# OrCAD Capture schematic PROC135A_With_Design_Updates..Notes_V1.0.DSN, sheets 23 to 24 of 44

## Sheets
23 23. CPSW RGMII_2 ETHERNET CONN.: size C; title: CPSW3G RGMII_2 ETHERNET PHY
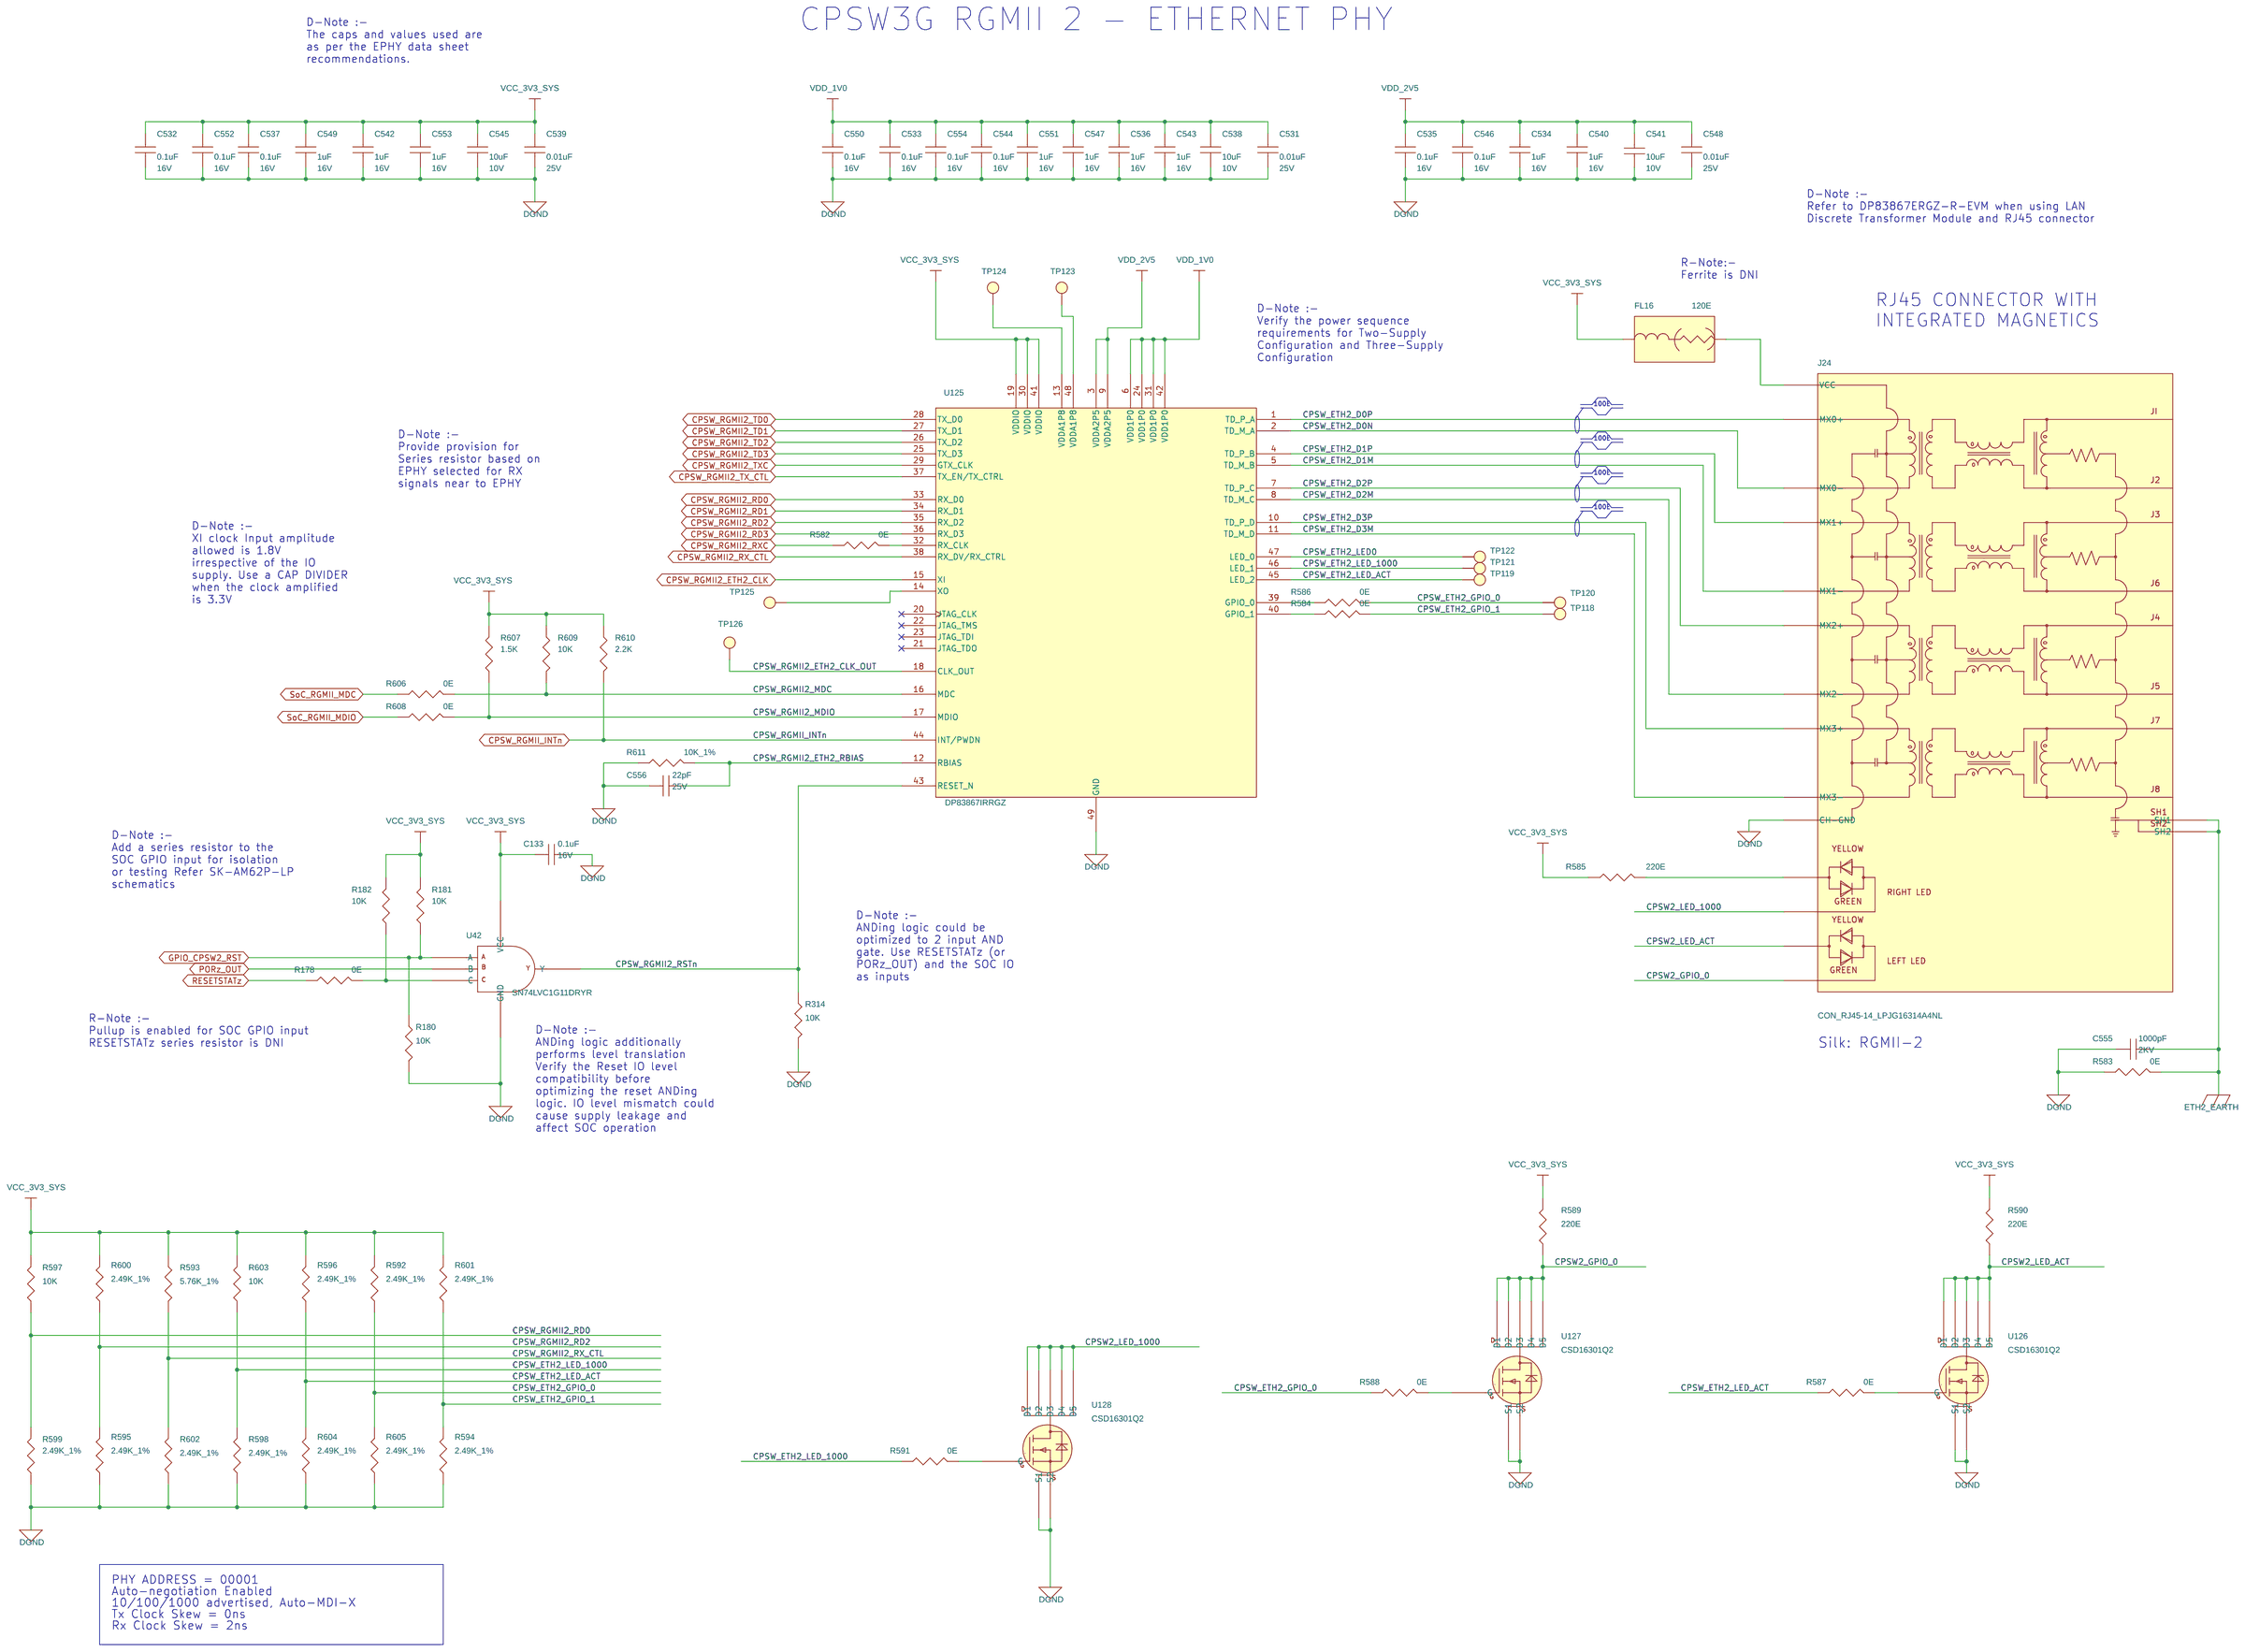
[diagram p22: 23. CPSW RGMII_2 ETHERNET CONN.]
24 24. PHY CLK & LED DRIVER: size C; title: SOC MAC INTERFACE, CLOCK BUFFER FOR SOC AND ETHERNET PHYS
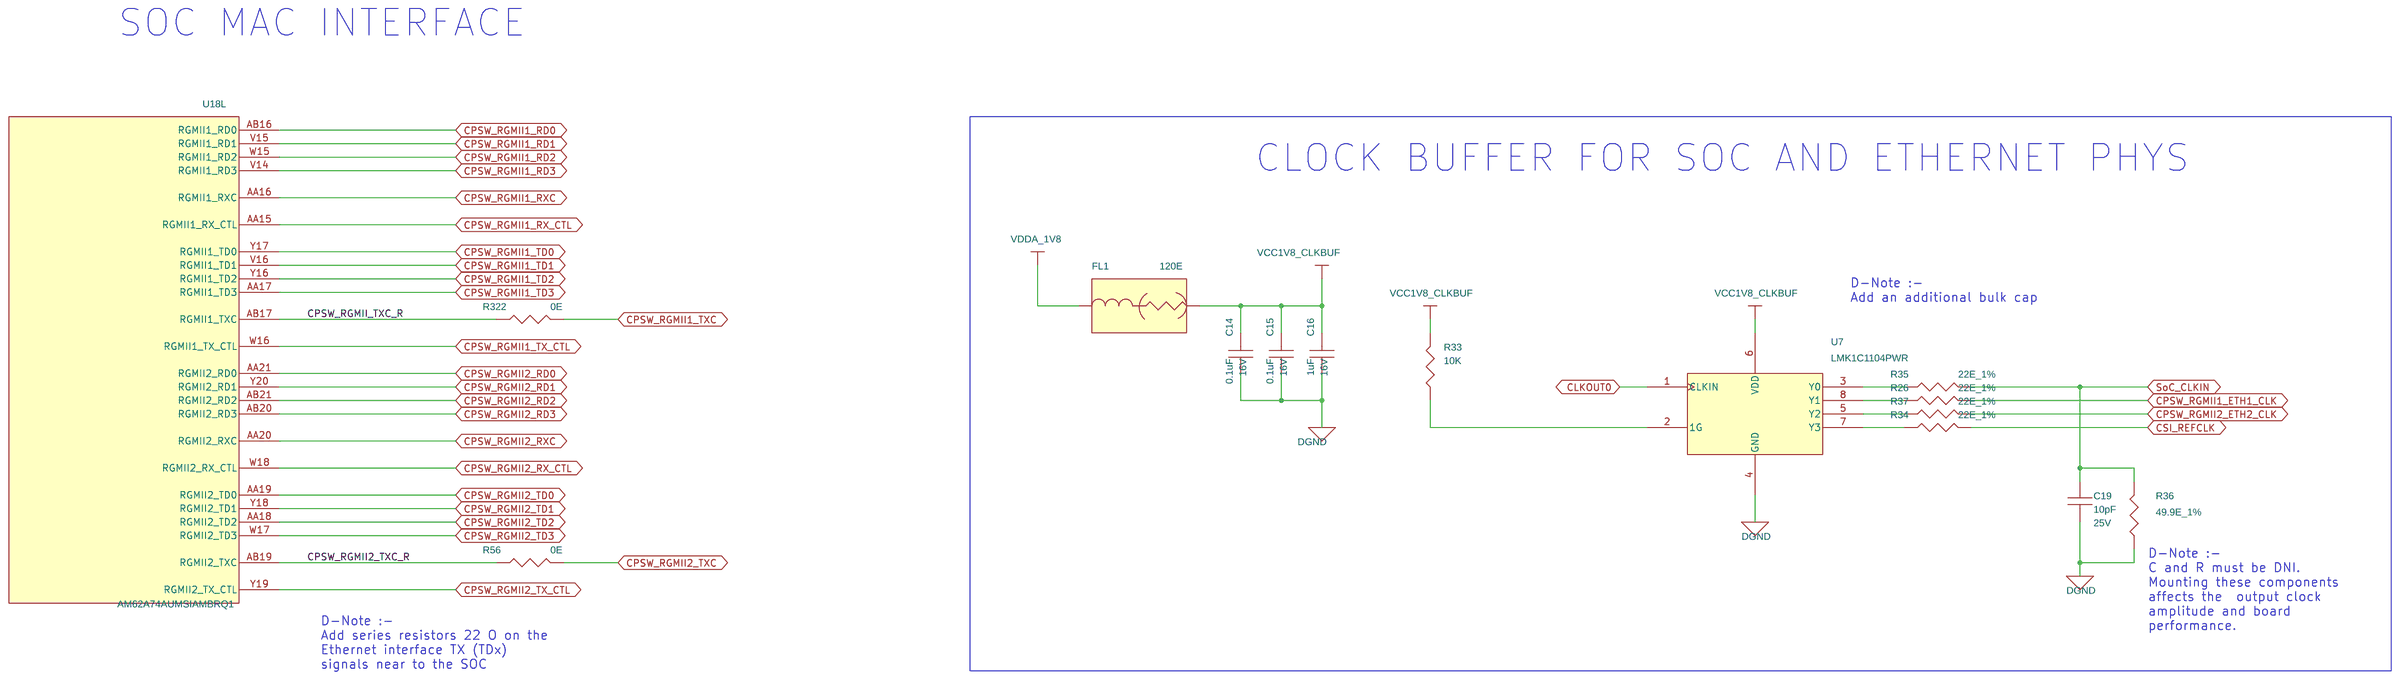
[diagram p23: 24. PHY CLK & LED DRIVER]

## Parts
sheet 23. CPSW RGMII_2 ETHERNET CONN.
C133  0.1uF  [CAP0201_0-5]
C531  0.01uF  [CAP0201_0-5]
C532  0.1uF  [CAP0201_0-5]
C533  0.1uF  [CAP0201_0-5]
C534  1uF  [CAP0201_0-5]
C535  0.1uF  [CAP0201_0-5]
C536  1uF  [CAP0201_0-5]
C537  0.1uF  [CAP0201_0-5]
C538  10uF  [CAP0402_0-75]
C539  0.01uF  [CAP0201_0-5]
C540  1uF  [CAP0201_0-5]
C541  10uF  [CAP0402_0-75]
C542  1uF  [CAP0201_0-5]
C543  1uF  [CAP0201_0-5]
C544  0.1uF  [CAP0201_0-5]
C545  10uF  [CAP0402_0-75]
C546  0.1uF  [CAP0201_0-5]
C547  1uF  [CAP0201_0-5]
C548  0.01uF  [CAP0201_0-5]
C549  1uF  [CAP0201_0-5]
C550  0.1uF  [CAP0201_0-5]
C551  1uF  [CAP0201_0-5]
C552  0.1uF  [CAP0201_0-5]
C553  1uF  [CAP0201_0-5]
C554  0.1uF  [CAP0201_0-5]
C555  1000pF  [CAP1206_1-75]
C556  22pF  [CAP0201_0-5]
FL16  120E  [EMIFIL_BLM15P_0402]
J24  CON_RJ45-14_LPJG16314A4NL  [CON_RJ45-14_LPJG16314A4NL_S_R_T_13-6]
R178  0E  [RES0201_0-5]
R180  10K  [RES0201_0-5]
R181  10K  [RES0201_0-5]
R182  10K  [RES0201_0-5]
R314  10K  [RES0201_0-5]
R582  0E  [RES0201_0-5]
R583  0E  [RES0603_0-75]
R584  0E  [RES0201_0-5]
R585  220E  [RES0402_0-5]
R586  0E  [RES0201_0-5]
R587  0E  [RES0402_0-5]
R588  0E  [RES0402_0-5]
R589  220E  [RES0402_0-5]
R590  220E  [RES0402_0-5]
R591  0E  [RES0402_0-5]
R592  2.49K_1%  [RES0402_0-5]
R593  5.76K_1%  [RES0402_0-5]
R594  2.49K_1%  [RES0402_0-5]
R595  2.49K_1%  [RES0402_0-5]
R596  2.49K_1%  [RES0402_0-5]
R597  10K  [RES0201_0-5]
R598  2.49K_1%  [RES0402_0-5]
R599  2.49K_1%  [RES0402_0-5]
R600  2.49K_1%  [RES0402_0-5]
R601  2.49K_1%  [RES0402_0-5]
R602  2.49K_1%  [RES0402_0-5]
R603  10K  [RES0201_0-5]
R604  2.49K_1%  [RES0402_0-5]
R605  2.49K_1%  [RES0402_0-5]
R606  0E  [RES0402_0-5]
R607  1.5K  [RES0201_0-5]
R608  0E  [RES0402_0-5]
R609  10K  [RES0201_0-5]
R610  2.2K  [RES0201_0-5]
R611  10K_1%  [RES0402_0-5]
TP118  TP20_SMD  [TP20_SMD]
TP119  TP20_SMD  [TP20_SMD]
TP120  TP20_SMD  [TP20_SMD]
TP121  TP20_SMD  [TP20_SMD]
TP122  TP20_SMD  [TP20_SMD]
TP123  TP20_SMD  [TP20_SMD]
TP124  TP20_SMD  [TP20_SMD]
TP125  TP20_SMD  [TP20_SMD]
TP126  TP20_SMD  [TP20_SMD]
U42  SN74LVC1G11DRYR  [SON6_SN74LVC2G17_40X60_0-6]
U125  DP83867IRRGZ  [QFN48_19-68_280X280_1]
U126  CSD16301Q2  [WSON6_CSD13202Q2_80X80_0-8]
U127  CSD16301Q2  [WSON6_CSD13202Q2_80X80_0-8]
U128  CSD16301Q2  [WSON6_CSD13202Q2_80X80_0-8]
sheet 24. PHY CLK & LED DRIVER
C14  0.1uF  [CAP0201_0-5]
C15  0.1uF  [CAP0201_0-5]
C16  1uF  [CAP0201_0-5]
C19  10pF  [CAP0201_0-5]
FL1  120E  [EMIFIL_BLM15A_0402_0-6]
R26  22E_1%  [RES0201_0-5]
R33  10K  [RES0201_0-5]
R34  22E_1%  [RES0201_0-5]
R35  22E_1%  [RES0201_0-5]
R36  49.9E_1%  [RES0402_0-5]
R37  22E_1%  [RES0201_0-5]
R56  0E  [RES0201_0-5]
R322  0E  [RES0201_0-5]
U7  LMK1C1104PWR  [TSSOP8_25-59_125X180_1-2]
sheet 41. OSCILLATOR
U18  AM62A74AUMSIAMBRQ1  [FBGA484_31-49_710X710_2-7]  (sections A,B,C,D,E,F,G,H,I,J,K,L,M,N,O,P,Q)

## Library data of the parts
C14 C15 C133 C532 C533 C535 C537 C544 C546 C550 C552 C554 = CAP: CAP CERAMIC 0.1uF 16V 10% X5R 0201; Alt_Mfr_name: YAGEO AMERICA; Alt_Mfr_part_number: CC0402KRX5R8BB104; Chkd/date: MANIRAJA/230118; Crtd /date: MANIRAJA/230118; Custom_Duty: 15%; Customs_HS_Code: 85322990; Distributor_name: DIGIKEY; Distributor_part_number: 490-14305-1-ND; Footprint Path: Y:\MIS_DATABASE\Library\ALTIUM_TOOL\PCB_FOOTPRINTS\Altium_Footprint_Lib.PcbLib; Height: 0.33MM; Library Path: Y:\MIS_DATABASE\Library\ALTIUM_TOOL\SCHEMATICS_PARTS\MS_DISCRETE_Library.schlib; Mfr_name: MURATA; Mfr_part_number: GRM033R61C104KE14D; Mistral Part No: 120009030072-R; Package: 0201; Part_type: CAPACITORS\CERAMIC; Project: TI_MAXIE_CPB; RoHS: RoHS; Temperature: -55°C+85°C; Tolerance: 10%; Voltage: 16V; Wattage: NA; Weight: 0.33mg; Datasheet: Y:\MIS_DATABASE\DATASHEETS\CAPACITORS\GRM033R61C104KE14.PDF
C531 C539 C548 = CAP: CAP CERAMIC 0.01uF 25V 10% X5R 0201; Chkd/date: MANIRAJA/230118; Crtd /date: MANIRAJA/230118; Custom_Duty: 15%; Customs_HS_Code: 85322990; Distributor_name: DIGIKEY; Distributor_part_number: GRM033R61E103KA12J-ND; Footprint Path: Y:\MIS_DATABASE\Library\ALTIUM_TOOL\PCB_FOOTPRINTS\Altium_Footprint_Lib.PcbLib; Height: 0.33MM; Library Path: Y:\MIS_DATABASE\Library\ALTIUM_TOOL\SCHEMATICS_PARTS\MS_DISCRETE_Library.schlib; Mfr_name: MURATA; Mfr_part_number: GRM033R61E103KA12J; Mistral Part No: 120018010007-R; Package: 0201; Part_type: CAPACITORS\CERAMIC; Project: TI_MAXIE_CPB; RoHS: RoHS; Temperature: -55°C+85°C; Tolerance: 10%; Voltage: 25V; Wattage: NA; Weight: 0.33mg; Datasheet: Y:\MIS_DATABASE\DATASHEETS\CAPACITORS\GRM033R61E103KA12.PDF
C16 C534 C536 C540 C542 C543 C547 C549 C551 C553 = CAP: CAP CERAMIC 1uF 16V 20% X5R 0201; Chkd/date: MANIRAJA/300520; Crtd /date: ALVY/260520; Custom_Duty: 15%; Customs_HS_Code: 85322990; Distributor_name: DIGIKEY; Distributor_part_number: 490-18654-1-ND; Footprint Path: Y:\MIS_DATABASE\Library\ALTIUM_TOOL\PCB_FOOTPRINTS\Altium_Footprint_Lib.PcbLib; Height: 0.39MM; Library Path: Y:\MIS_DATABASE\Library\ALTIUM_TOOL\SCHEMATICS_PARTS\MS_DISCRETE_Library.schlib; Mfr_name: MURATA; Mfr_part_number: GRM033R61C105ME15D; Mistral Part No: 120018090038-R; Package: 0201; Part_type: CAPACITORS\CERAMIC; Project: QCS610_NANOSOM; RoHS: RoHS; Temperature: -55°C+85°C; Tolerance: 20%; Voltage: 16V; Wattage: NA; Weight: 0.33mg; Datasheet: Y:\MIS_DATABASE\DATASHEETS\CAPACITORS\GRM033R61C105ME15.PDF
C538 C541 C545 = CAP: CAP CERAMIC 10uF 10V 20% X5R 0402; Chkd/date: MANIRAJA/300520; Crtd /date: ALVY/260520; Custom_Duty: 15%; Customs_HS_Code: 85322990; Distributor_name: DIGIKEY; Distributor_part_number: 490-GRM155R61A106ME11DTR-ND; Footprint Path: Y:\MIS_DATABASE\Library\ALTIUM_TOOL\PCB_FOOTPRINTS\Altium_Footprint_Lib.PcbLib; Height: 0.55MM; Library Path: Y:\MIS_DATABASE\Library\ALTIUM_TOOL\SCHEMATICS_PARTS\MS_DISCRETE_Library.schlib; Mfr_name: MURATA; Mfr_part_number: GRM155R61A106ME11D; Mistral Part No: 120013110019-R; Package: 0402; Part_type: CAPACITORS\CERAMIC; Project: QCS610_NANOSOM; RoHS: RoHS; Temperature: -55°C+85°C; Tolerance: 20%; Voltage: 10V; Wattage: NA; Weight: 3.1mg; Datasheet: Y:\MIS_DATABASE\DATASHEETS\CAPACITORS\MURATA-GXX-SER_NOV17.PDF
C555 = CAP: CAP CERAMIC 1000pF 2KV 10% X7R 1206; Chkd/date: SHREESHAIL/291106; Crtd /date: MAZHAR/281106; Custom_Duty: 15%; Customs_HS_Code: 85322990; Distributor_name: DIGIKEY; Distributor_part_number: 478-2956-1-ND; Footprint Path: Y:\MIS_DATABASE\Library\ALTIUM_TOOL\PCB_FOOTPRINTS\Altium_Footprint_Lib.PcbLib; Height: 1.52MM; Library Path: Y:\MIS_DATABASE\Library\ALTIUM_TOOL\SCHEMATICS_PARTS\MS_DISCRETE_Library.schlib; Mfr_name: AVX CORPORATION; Mfr_part_number: 1206GC102KAT1A; Mistral Part No: 120015080006-R; Package: 1206; Part_type: CAPACITORS\CERAMIC; Project: ADR1B; RoHS: RoHS; Temperature: -55°C+125°C; Tolerance: 10%; Voltage: 2KV; Wattage: NA; Weight: 16.2mg; Datasheet: Y:\MIS_DATABASE\DATASHEETS\CAPACITORS\AVX_HV-MLC.PDF
C556 = CAP: CAP CERAMIC 22pF 25V 1% C0G(NP0) 0201; Chkd/date: MANIRAJA/270721; Crtd /date: ALVY/260721; Custom_Duty: 15%; Customs_HS_Code: 85322990; Distributor_name: DIGIKEY; Distributor_part_number: 490-14545-1-ND; Footprint Path: Y:\MIS_DATABASE\Library\ALTIUM_TOOL\PCB_FOOTPRINTS\Altium_Footprint_Lib.PcbLib; Height: 0.33MM; Library Path: Y:\MIS_DATABASE\Library\ALTIUM_TOOL\SCHEMATICS_PARTS\MS_DISCRETE_Library.schlib; Mfr_name: MURATA; Mfr_part_number: GRM0335C1E220FA01D; Mistral Part No: 120021070019-R; Package: 0201; Part_type: CAPACITORS\CERAMIC; Project: TI_AM335x SK_BRD; RoHS: RoHS; Temperature: -55°C+125°C; Tolerance: 1%; Voltage: 25V; Wattage: NA; Weight: 0.33mg; Datasheet: Y:\MIS_DATABASE\DATASHEETS\CAPACITORS\GRM0335C1E220FA01.PDF
FL16 = EMIFILTER_IND: FERRITE CHIP 120E 2A 0402; Chkd/date: NAVEED/241114; Crtd /date: USMAN/170613; Custom_Duty: 24%; Customs_HS_Code: 85369090; Distributor_name: MOUSER; Distributor_part_number: 81-BLM15PX121SN1D; Height: 0.55MM; Mfr_name: MURATA; Mfr_part_number: BLM15PX121SN1D; Mistral Part No: 130013060022-R; Package: 0402; Part_type: FILTER; Project: GEN_3-8; RoHS: RoHS; Temperature: -55°C+125°C; Tolerance: 25%; Voltage: NA; Wattage: NA; Weight: NA; Datasheet: Y:\MIS_DATABASE\DATASHEETS\DISCRETES\INDUCTORS\BLM15X.PDF
J24 = CON_RJ45-14_LPJG16314A4NL: CON RJ-45 FEMALE 14POS RT TH; Chkd/date: VASANTHA/150714; Crtd /date: BALACHANDAR/120614; Custom_Duty: 24%; Customs_HS_Code: 85369090; Distributor_name: NA; Distributor_part_number: NA; Footprint Path: Y:\MIS_DATABASE\Library\ALTIUM_TOOL\PCB_FOOTPRINTS\Altium_Footprint_Lib.PcbLib; Height: 13.60MM; Library Path: Y:\MIS_DATABASE\Library\ALTIUM_TOOL\SCHEMATICS_PARTS\MS_CONNECTOR_Library.schlib; Mfr_name: LINK-PP; Mfr_part_number: LPJG16314A4NL; Mistral Part No: 150014060029-R; Package: THRU-HOLE; Part_type: CONNECTOR\JACK; Project: AEGIS; RoHS: RoHS; Temperature: -0°C+70°C; Tolerance: NA; Voltage: NA; Wattage: NA; Weight: NA; Datasheet: Y:\MIS_DATABASE\DATASHEETS\CONNECTORS\LPJG16314A4NL.PDF
R178 R584 R586 = RESISTOR: RES 0E 1/20W 5% 0201; Chkd/date: NAVEED/301214; Crtd /date: MUDDU/120710; Custom_Duty: 15%; Customs_HS_Code: 85332119; Distributor_name: DIGIKEY; Distributor_part_number: 311-0.0NCT-ND; Footprint Path: Y:\MIS_DATABASE\Library\ALTIUM_TOOL\PCB_FOOTPRINTS\Altium_Footprint_Lib.PcbLib; Height: 0.26MM; Library Path: Y:\MIS_DATABASE\Library\ALTIUM_TOOL\SCHEMATICS_PARTS\MS_DISCRETE_Library.schlib; Mfr_name: YAGEO AMERICA; Mfr_part_number: RC0201JR-070RL; Mistral Part No: 110010070067-R; Package: 0201; Part_type: RESISTORS\FIXED; Project: PB_BUGBASE; RoHS: RoHS; Temperature: -55°C+125°C; Tolerance: 5%; Voltage: NA; Wattage: 1/20W; Weight: 0.17mg; Datasheet: Y:\MIS_DATABASE\DATASHEETS\RESISTORS\RCXXXXL-SER_MAR18.PDF
R33 R180-R182 R314 R597 R603 R609 = RESISTOR: RES 10K 1/20W 5% 0201; Chkd/date: MANIRAJA/050517; Crtd /date: MANIRAJA/050517; Custom_Duty: 15%; Customs_HS_Code: 85332119; Distributor_name: DIGIKEY; Distributor_part_number: 311-10KNCT-ND; Footprint Path: Y:\MIS_DATABASE\Library\ALTIUM_TOOL\PCB_FOOTPRINTS\Altium_Footprint_Lib.PcbLib; Height: 0.26MM; Library Path: Y:\MIS_DATABASE\Library\ALTIUM_TOOL\SCHEMATICS_PARTS\MS_DISCRETE_Library.schlib; Mfr_name: YAGEO AMERICA; Mfr_part_number: RC0201JR-0710KL; Mistral Part No: 110010070051-R; Package: 0201; Part_type: RESISTORS\FIXED; Project: GOLDEN-I LITE; RoHS: RoHS; Temperature: -55°C+125°C; Tolerance: 5%; Voltage: NA; Wattage: 1/20W; Weight: 0.17mg; Datasheet: Y:\MIS_DATABASE\DATASHEETS\RESISTORS\RCXXXXL-SER_MAR18.PDF
R56 R322 R582 = RESISTOR: RES 0E 1/20W 5% 0201; Chkd/date: NAVEED/301214; Crtd /date: MUDDU/120710; Custom_Duty: 15%; Customs_HS_Code: 85332119; Distributor_name: DIGIKEY; Distributor_part_number: 311-0.0NCT-ND; Footprint Path: Y:\MIS_DATABASE\Library\ALTIUM_TOOL\PCB_FOOTPRINTS\Altium_Footprint_Lib.PcbLib; Height: 0.26MM; Library Path: Y:\MIS_DATABASE\Library\ALTIUM_TOOL\SCHEMATICS_PARTS\MS_DISCRETE_Library.schlib; Mfr_name: YAGEO AMERICA; Mfr_part_number: RC0201JR-070RL; Mistral Part No: 110010070067-R; Package: 0201; Part_type: RESISTORS\FIXED; Project: PB_BUGBASE; RoHS: RoHS; SIGNAL_MODEL: RESISTOR_RES0201_0-5_0E_0E; Temperature: -55°C+125°C; Tolerance: 5%; Voltage: NA; Wattage: 1/20W; Weight: 0.17mg; Datasheet: Y:\MIS_DATABASE\DATASHEETS\RESISTORS\RCXXXXL-SER_MAR18.PDF
R583 = RESISTOR: RES 0E 1/10W 5% 0603; Chkd/date: MANIRAJA/051217; Crtd /date: BAVISH/180211; Custom_Duty: 15%; Customs_HS_Code: 85332119; Distributor_name: DIGIKEY; Distributor_part_number: 311-0.0GRCT-ND; Footprint Path: Y:\MIS_DATABASE\Library\ALTIUM_TOOL\PCB_FOOTPRINTS\Altium_Footprint_Lib.PcbLib; Height: 0.55MM; Library Path: Y:\MIS_DATABASE\Library\ALTIUM_TOOL\SCHEMATICS_PARTS\MS_DISCRETE_Library.schlib; Manufacturer: YAGEO AMERICA; Mfr_name: PANASONIC-ECG; Mfr_part_number: RC0603JR-070RL; Mistral Part No: 110011020013-R; Package: 0603; Part_type: RESISTORS\FIXED; Project: KENNEL; RoHS: RoHS; Temperature: -55°C+155°C; Tolerance: 5%; Voltage: NA; Wattage: 1/10W; Weight: 2mg; Datasheet: Y:\MIS_DATABASE\DATASHEETS\RESISTORS\RCXXXXL-SER_MAR18.PDF
R585 R589 R590 = RESISTOR: RES 220E 1/10W 5% 0402; Chkd/date: VASANTHA/291216; Crtd /date: GEETHA/260406; Custom_Duty: 15%; Customs_HS_Code: 85332119; Distributor_name: DIGIKEY; Distributor_part_number: P220JCT-ND; Footprint Path: Y:\MIS_DATABASE\Library\ALTIUM_TOOL\PCB_FOOTPRINTS\Altium_Footprint_Lib.PcbLib; Height: 0.40MM; Library Path: Y:\MIS_DATABASE\Library\ALTIUM_TOOL\SCHEMATICS_PARTS\MS_DISCRETE_Library.schlib; Mfr_name: PANASONIC-ECG; Mfr_part_number: ERJ-2GEJ221X; Mistral Part No: 110009030506-R; Package: 0402; Part_type: RESISTORS\FIXED; Project: RED EYE; RoHS: RoHS; Temperature: -55°C+155°C; Tolerance: 5%; Voltage: NA; Wattage: 1/10W; Weight: 0.8mg; Datasheet: Y:\MIS_DATABASE\DATASHEETS\RESISTORS\PAN-ERJSER_NOV17.PDF
R587 R588 R591 R606 R608 = RESISTOR: RES 0E 1/16W JUMPER 0402; Chkd/date: VASANTHA/201216; Crtd /date: MUDDU/190810; Custom_Duty: 15%; Customs_HS_Code: 85332119; Distributor_name: DIGIKEY; Distributor_part_number: 541-0.0JCT-ND; Footprint Path: Y:\MIS_DATABASE\Library\ALTIUM_TOOL\PCB_FOOTPRINTS\Altium_Footprint_Lib.PcbLib; Height: 0.40MM; Library Path: Y:\MIS_DATABASE\Library\ALTIUM_TOOL\SCHEMATICS_PARTS\MS_DISCRETE_Library.schlib; Mfr_name: VISHAY; Mfr_part_number: CRCW04020000Z0ED; Mistral Part No: 110010080019-R; Package: 0402; Part_type: RESISTORS\FIXED; Project: PB_BUGBASE; RoHS: RoHS; Temperature: -55°C+155°C; Tolerance: NA; Voltage: NA; Wattage: 1/16W; Weight: 0.65mg; Datasheet: Y:\MIS_DATABASE\DATASHEETS\RESISTORS\CRCW0603.PDF
R592 R594-R596 R598-R602 R604 R605 = RESISTOR: RES 2.49K 1/16W 1% 0402; Chkd/date: VASANTHA/270516; Crtd /date: VASANTHA/270516; Custom_Duty: 15%; Customs_HS_Code: 85332119; Distributor_name: DIGIKEY; Distributor_part_number: 311-2.49KLRCT-ND; Footprint Path: Y:\MIS_DATABASE\Library\ALTIUM_TOOL\PCB_FOOTPRINTS\Altium_Footprint_Lib.PcbLib; Height: 0.40MM; Library Path: Y:\MIS_DATABASE\Library\ALTIUM_TOOL\SCHEMATICS_PARTS\MS_DISCRETE_Library.schlib; Mfr_name: YAGEO AMERICA; Mfr_part_number: RC0402FR-072K49L; Mistral Part No: 110016050020-R; Package: 0402; Part_type: RESISTORS\FIXED; Project: TMDXCSKCC; RoHS: RoHS; Temperature: -55°C+155°C; Tolerance: 1%; Voltage: NA; Wattage: 1/16W; Weight: 0.65mg; Datasheet: Y:\MIS_DATABASE\DATASHEETS\RESISTORS\RCXXXXL-SER_MAR18.PDF
R593 = RESISTOR: RES 5.76K 1/10W 1% 0402; Chkd/date: MAZHAR/150709; Crtd /date: USMAN/220808; Custom_Duty: 15%; Customs_HS_Code: 85332119; Distributor_name: DIGIKEY; Distributor_part_number: P5.76KLCT-ND; Footprint Path: Y:\MIS_DATABASE\Library\ALTIUM_TOOL\PCB_FOOTPRINTS\Altium_Footprint_Lib.PcbLib; Height: 0.40MM; Library Path: Y:\MIS_DATABASE\Library\ALTIUM_TOOL\SCHEMATICS_PARTS\MS_DISCRETE_Library.schlib; Mfr_name: PANASONIC-ECG; Mfr_part_number: ERJ-2RKF5761X; Mistral Part No: 110009030945-R; Package: 0402; Part_type: RESISTORS\FIXED; Project: CPB; RoHS: RoHS; Temperature: -55°C+155°C; Tolerance: 1%; Voltage: NA; Wattage: 1/10W; Weight: 0.8mg; Datasheet: Y:\MIS_DATABASE\DATASHEETS\RESISTORS\PAN-ERJSER_NOV17.PDF
R607 = RESISTOR: RES 1.5K 1/20W 5% 0201; Chkd/date: MAZHAR/130208; Crtd /date: USMAN/130208; Custom_Duty: 15%; Customs_HS_Code: 85332119; Distributor_name: DIGIKEY; Distributor_part_number: P1.5KAGCT-ND; Footprint Path: Y:\MIS_DATABASE\Library\ALTIUM_TOOL\PCB_FOOTPRINTS\Altium_Footprint_Lib.PcbLib; Height: 0.26MM; Library Path: Y:\MIS_DATABASE\Library\ALTIUM_TOOL\SCHEMATICS_PARTS\MS_DISCRETE_Library.schlib; Manufacturer: PANASONIC-ECG; Mfr_name: PANASONIC-ECG; Mfr_part_number: ERJ-1GEJ152C; Mistral Part No: 110010070057-R; Package: 0201; Part_type: RESISTORS\FIXED; Project: SMART VIEW_IP CAMERA; RoHS: RoHS; Temperature: -55°C+125°C; Tolerance: 5%; Voltage: NA; Wattage: 1/20W; Weight: 0.15mg; Datasheet: Y:\MIS_DATABASE\DATASHEETS\RESISTORS\PAN-ERJXGE-FEB06.PDF
R610 = RESISTOR: RES 2.2K 1/20W 5% 0201; Chkd/date: VASANTHA/010117; Crtd /date: MAZHAR/010605; Custom_Duty: 15%; Customs_HS_Code: 85332119; Distributor_name: DIGIKEY; Distributor_part_number: P2.2KAGCT-ND; Footprint Path: Y:\MIS_DATABASE\Library\ALTIUM_TOOL\PCB_FOOTPRINTS\Altium_Footprint_Lib.PcbLib; Height: 0.26MM; Library Path: Y:\MIS_DATABASE\Library\ALTIUM_TOOL\SCHEMATICS_PARTS\MS_DISCRETE_Library.schlib; Mfr_name: PANASONIC-ECG; Mfr_part_number: ERJ-1GEJ222C; Mistral Part No: 110009030427-R; Package: 0201; Part_type: RESISTORS\FIXED; Project: G4SLIM; RoHS: RoHS; Temperature: -55°C+125°C; Tolerance: 5%; Voltage: NA; Wattage: 1/20W; Weight: 0.15mg; Datasheet: Y:\MIS_DATABASE\DATASHEETS\RESISTORS\PAN-ERJXGE-FEB06.PDF
R611 = RESISTOR: RES 10K 1/10W 1% AUTO 0402; Chkd/date: MANIRAJA/191020; Crtd /date: ALVY/191020; Custom_Duty: 15%; Customs_HS_Code: 85332119; Distributor_name: DIGIKEY; Distributor_part_number: MCS0402-10.0K-MFCT-ND; Footprint Path: Y:\MIS_DATABASE\Library\ALTIUM_TOOL\PCB_FOOTPRINTS\Altium_Footprint_Lib.PcbLib; Height: 0.37MM; Library Path: Y:\MIS_DATABASE\Library\ALTIUM_TOOL\SCHEMATICS_PARTS\MS_DISCRETE_Library.schlib; Manufacturer: YAGEO AMERICA; Mfr_name: VISHAY; Mfr_part_number: MCS0402MC1002FE000; Mistral Part No: 110020100039-R; Package: 0402; Part_type: RESISTORS\FIXED; Project: MCX_80MHz_ADC_DRIVER; RoHS: RoHS; Temperature: -55°C+175°C; Tolerance: 1%; Voltage: NA; Wattage: 1/10W; Weight: 0.65mg; Datasheet: Y:\MIS_DATABASE\DATASHEETS\RESISTORS\MCTXXXXM-SER.PDF
TP118-TP122 TP126 = TESTPOINT: TESTPOINT CIR 20 SMD; Chkd/date: SHREESHAIL/171006; Crtd /date: MAZHAR/171006; Custom_Duty: NA; Customs_HS_Code: NA; Distributor_name: NA; Distributor_part_number: NA; Footprint Path: Y:\MIS_DATABASE\Library\ALTIUM_TOOL\PCB_FOOTPRINTS\Altium_Footprint_Lib.PcbLib; Height: NA; Library Path: Y:\MIS_DATABASE\Library\ALTIUM_TOOL\SCHEMATICS_PARTS\MS_DISCRETE_Library.schlib; MECHANICAL 3D STEP FILE: NA; Mfr_name: LOCAL; Mistral Part No: NA; Package: SMD; Project: BT MODULE_CSRBC04; RoHS: NA; Temperature: NA; Tolerance: NA; Voltage: NA; Wattage: NA; Weight: NA; Datasheet: NA
TP123-TP125 = TESTPOINT: TESTPOINT CIR 20 SMD; Chkd/date: SHREESHAIL/171006; Crtd /date: MAZHAR/171006; Custom_Duty: NA; Customs_HS_Code: NA; Distributor_name: NA; Distributor_part_number: NA; Footprint Path: Y:\MIS_DATABASE\Library\ALTIUM_TOOL\PCB_FOOTPRINTS\Altium_Footprint_Lib.PcbLib; Height: NA; Library Path: Y:\MIS_DATABASE\Library\ALTIUM_TOOL\SCHEMATICS_PARTS\MS_DISCRETE_Library.schlib; MECHANICAL 3D STEP FILE: NA; Manufacturer: LOCAL; Mfr_name: LOCAL; Mistral Part No: NA; Package: SMD; Project: BT MODULE_CSRBC04; RoHS: NA; Temperature: NA; Tolerance: NA; Voltage: NA; Wattage: NA; Weight: NA; Datasheet: NA
U42 = SN74LVC1G11DCKR_SC70-6: IC SINGLE 3-INPUT POSITIVE-AND GATE SON6; Chkd/date: MANIRAJA/270121; Crtd /date: ALVY/270121; Custom_Duty: 15%; Customs_HS_Code: 85423100; Distributor_name: DIGIKEY; Distributor_part_number: 296-30120-1-ND; Footprint Path: Y:\MIS_DATABASE\Library\ALTIUM_TOOL\PCB_FOOTPRINTS\Altium_Footprint_Lib.PcbLib; Height: 0.60MM; Library Path: Y:\MIS_DATABASE\Library\ALTIUM_TOOL\SCHEMATICS_PARTS\MS_GATE_Library.schlib; Mfr_name: TEXAS INSTRUMENTS; Mistral Part No: 141021010013-R; Package: SON6; Part_type: ICS\DIGITAL\GATES; Project: AM64X_SKEVM; RoHS: RoHS; Temperature: -40°C+125°C; Tolerance: NA; Voltage: NA; Wattage: NA; Weight: 33mg; Datasheet: Y:\MIS_DATABASE\DATASHEETS\ICS\DIGITAL\GATES\SN74LVC1G_NOV16.PDF
U125 = DP83867IRRGZ_VQFN48: IC HIGH IMMUNITY 10/100/1000 Mb/s ETHERNET PHY LAYER TRANSCEIVER VQFN48; Chkd/date: MANIRAJA/110817; Crtd /date: MANIRAJA/110817; Custom_Duty: 15%; Customs_HS_Code: 85423100; Distributor_name: DIGIKEY; Distributor_part_number: DP83867IRRGZT-ND; Height: 1.00MM; Mfr_name: TEXAS INSTRUMENTS; Mistral Part No: 143017080002-R; Package: VQFN48; Part_type: ICS\TELECOM\TRANSCEIVER; Project: TI_SVB_CONTROLLER CARD; RoHS: RoHS; Temperature: -40°C+85°C; Tolerance: NA; Voltage: NA; Wattage: NA; Weight: NA; Datasheet: Y:\MIS_DATABASE\DATASHEETS\ICS\DIGITAL\BUSTRANSCEIVER\DP83867I.PDF
U126-U128 = MOSFET_CSD17313Q2: IC MOSFET N-CHANNEL NEXFET 25V WSON6; Chkd/date: ALVY/071220; Crtd /date: MANIRAJA/071220; Custom_Duty: 15%; Customs_HS_Code: 85423100; Distributor_name: DIGIKEY; Distributor_part_number: 296-25260-1-ND; Footprint Path: Y:\MIS_DATABASE\Library\ALTIUM_TOOL\PCB_FOOTPRINTS\Altium_Footprint_Lib.PcbLib; Height: 0.80MM; Library Path: Y:\MIS_DATABASE\Library\ALTIUM_TOOL\SCHEMATICS_PARTS\MS_MOSFET_Library.schlib; Mfr_name: TEXAS INSTRUMENTS; Mistral Part No: 142020120008-R; Package: WSON6; Part_type: ICS\POWER\MOSFET; Project: TI_AM243x LP EVM; RoHS: RoHS; Temperature: -55°C+150°C; Tolerance: NA; Voltage: NA; Wattage: NA; Weight: 8.7mg; Datasheet: Y:\MIS_DATABASE\DATASHEETS\ICS\POWER\CSD16301Q2.PDF
C19 = CAP: CAP CERAMIC 10pF 25V 5% HI-Q C0G(NP0) 0201; Chkd/date: VASANTHA/081216; Crtd /date: MANIRAJA/081216; Custom_Duty: 15%; Customs_HS_Code: 85322990; Distributor_name: DIGIKEY; Distributor_part_number: 490-13312-1-ND; Footprint Path: Y:\MIS_DATABASE\Library\ALTIUM_TOOL\PCB_FOOTPRINTS\Altium_Footprint_Lib.PcbLib; Height: 0.33MM; Library Path: Y:\MIS_DATABASE\Library\ALTIUM_TOOL\SCHEMATICS_PARTS\MS_DISCRETE_Library.schlib; Mfr_name: MURATA; Mfr_part_number: GJM0335C1E100JB01D; Mistral Part No: 120016120010-R; Package: 0201; Part_type: CAPACITORS\CERAMIC; Project: OCTBTS5200; RoHS: RoHS; Temperature: -55°C+125°C; Tolerance: 5%; Voltage: 25V; Wattage: NA; Weight: 0.33mg; Datasheet: Y:\MIS_DATABASE\DATASHEETS\CAPACITORS\MURATA-GXX-SER_NOV17.PDF
FL1 = EMIFILTER_IND: IND FERRITE BEAD CHIP 120E 2A 0402; Chkd/date: NAVEED/241114; Crtd /date: USMAN/170613; Custom_Duty: 24%; Customs_HS_Code: 85369090; Distributor_name: DIGIKEY; Distributor_part_number: 490-9656-1-ND; Footprint Path: Y:\MIS_DATABASE\Library\ALTIUM_TOOL\PCB_FOOTPRINTS\Altium_Footprint_Lib.PcbLib; Height: 0.55MM; Library Path: Y:\MIS_DATABASE\Library\ALTIUM_TOOL\SCHEMATICS_PARTS\MS_FILTER_Library.schlib; Mfr_name: MURATA; Mfr_part_number: BLM15PX121SN1D; Mistral Part No: 130013060022-R; Package: 0402; Part_type: INDUCTOR; Project: GEN_3-8; RoHS: RoHS; Temperature: -55°C+125°C; Tolerance: 25%; Voltage: NA; Wattage: NA; Weight: 1mg; Datasheet: Y:\MIS_DATABASE\DATASHEETS\DISCRETES\INDUCTORS\BLM15-SN1-SER.PDF
R26 R34 R35 R37 = RESISTOR: RES 22E 1/20W 1% 0201; Chkd/date: MANIRAJA/080319; Crtd /date: ALVY/080319; Custom_Duty: 15%; Customs_HS_Code: 85332119; Distributor_name: DIGIKEY; Distributor_part_number: YAG2518CT-ND; Footprint Path: Y:\MIS_DATABASE\Library\ALTIUM_TOOL\PCB_FOOTPRINTS\Altium_Footprint_Lib.PcbLib; Height: 0.26MM; Library Path: Y:\MIS_DATABASE\Library\ALTIUM_TOOL\SCHEMATICS_PARTS\MS_DISCRETE_Library.schlib; Mfr_name: YAGEO AMERICA; Mfr_part_number: RC0201FR-0722RL; Mistral Part No: 110009030522-R; Package: 0201; Part_type: RESISTORS\FIXED; Project: AM654x_SOM; RoHS: RoHS; Temperature: -55°C+125°C; Tolerance: 1%; Voltage: NA; Wattage: 1/20W; Weight: 0.17mg; Datasheet: Y:\MIS_DATABASE\DATASHEETS\RESISTORS\RCXXXXL-SER_MAR18.PDF
R36 = RESISTOR: RES 49.9E 1/16W 1% 0402; Chkd/date: MANIRAJA/210519; Crtd /date: MANIRAJA/210519; Custom_Duty: 15%; Customs_HS_Code: 85332119; Distributor_name: DIGIKEY; Distributor_part_number: 541-3967-1-ND; Footprint Path: Y:\MIS_DATABASE\Library\ALTIUM_TOOL\PCB_FOOTPRINTS\Altium_Footprint_Lib.PcbLib; Height: 0.35MM; Library Path: Y:\MIS_DATABASE\Library\ALTIUM_TOOL\SCHEMATICS_PARTS\MS_DISCRETE_Library.schlib; Mfr_name: VISHAY; Mfr_part_number: CRCW040249R9FKEDC; Mistral Part No: 110009030846-R; Package: 0402; Part_type: RESISTORS\FIXED; Project: RFSU_RFTJ_CARD; RoHS: RoHS; Temperature: -55°C+155°C; Tolerance: 1%; Voltage: NA; Wattage: 1/16W; Weight: 0.65mg; Datasheet: Y:\MIS_DATABASE\DATASHEETS\RESISTORS\CRCW_C-SER.PDF
U7 = LMK1C1104_TSSOP8: IC LVCMOS CLOCK BUFFER TSSOP8; Chkd/date: MANIRAJA/190520; Crtd /date: ALVY/190520; Custom_Duty: 15%; Customs_HS_Code: 85423100; Distributor_name: DIGIKEY; Distributor_part_number: 296-LMK1C1104PWRCT-ND; Footprint Path: Y:\MIS_DATABASE\Library\ALTIUM_TOOL\PCB_FOOTPRINTS\Altium_Footprint_Lib.PcbLib; Height: 1.20MM; Library Path: Y:\MIS_DATABASE\Library\ALTIUM_TOOL\SCHEMATICS_PARTS\MS_COMBINATIONAL_Library.schlib; Manufacturer: TEXAS INSTRUMENTS; Mfr_name: TEXAS INSTRUMENTS; Mistral Part No: 141020050011-R; Package: TSSOP8; Part_type: ICS\DIGITAL\COMBINATIONAL; Project: RETROFIT-RAD2; RoHS: RoHS; Temperature: -40°C+125°C; Tolerance: NA; Voltage: NA; Wattage: NA; Weight: 34.2mg; Datasheet: Y:\MIS_DATABASE\DATASHEETS\ICS\DIGITAL\COMBINATIONAL\LMK1C1104.PDF
U18 = AM62A-EVM_SOC_FCBGA484: IC AM62A SK EVM SoC MICROPROCESSOR FCBGA484; Chkd/date: PRADEEP/020823; Crtd /date: PRADEEP/020823; Custom_Duty: 15%; Customs_HS_Code: 85423100; Distributor_name: NA; Distributor_part_number: NA; Footprint Path: Y:\MIS_DATABASE\Library\ALTIUM_TOOL\PCB_FOOTPRINTS\Altium_Footprint_Lib.PcbLib; Height: 2.65MM; Library Ref: AM62A-EVM_SoC_FCBGA484; Mfr_name: TEXAS INSTRUMENTS; Mistral Part No: 141230080001-R; Package: FCBGA484; Part_type: ICS\DIGITAL\MICROPROCESSOR; Project: TI_AM62A_SK_EVM; RoHS: NA; Temperature: NA; Tolerance: NA; Voltage: NA; Wattage: NA; Weight: NA; Datasheet: Y:\MIS_DATABASE\DATASHEETS\ICS\DIGITAL\MICROCONTROLLER\AM62A_SK_EVM.PDF

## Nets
DGND: C14.1 C15.1 C16.1 C19.2 C133.2 C531.2 C532.2 C533.2 C534.2 C535.2 C536.2 C537.2 C538.2 C539.2 C540.2 C541.1 C542.2 C543.2 C544.2 C545.2 C546.2 C547.2 C548.2 C549.2 C550.2 C551.2 C552.2 C553.2 C554.2 C555.2 C556.1 J24.1(CH-GND) R36.1 R180.2 R314.2 R583.2 R594.1 R595.1 R598.1 R599.1 R602.1 R604.1 R605.1 R611.2 U7.4(GND) U42.2(GND) U125.49(GND) U126.4(S1) U126.7(S2) U127.4(S1) U127.7(S2) U128.4(S1) U128.7(S2) ; also on sheet 9 10 11 12 13 14 15 16 17 18 19 20 21 22 25 26 27 28 29 30 31 32 33 34 35 36 37 38 39 40 41 42 43
VCC1V8_CLKBUF: C14.2 C15.2 C16.2 FL1.2 R33.2 U7.6(VDD) ; also on sheet 41
VCC_3V3_SYS: C133.1 C532.1 C537.1 C539.1 C542.1 C545.1 C549.1 C552.1 C553.1 FL16.1 R181.2 R182.2 R585.1 R589.2 R590.2 R592.2 R593.1 R596.2 R597.2 R600.2 R601.2 R603.2 R607.2 R609.1 R610.1 U42.5(VCC) U125.19(VDDIO) U125.30(VDDIO) U125.41(VDDIO) ; also on sheet 9 10 12 13 17 18 19 21 22 25 26 28 29 30 32 33 34 35 36 37 38 39 40 41 42
VDD_1V0: C531.1 C533.1 C536.1 C538.1 C543.1 C544.1 C547.1 C550.1 C551.1 C554.1 U125.6(VDD1P0) U125.24(VDD1P0) U125.31(VDD1P0) U125.42(VDD1P0) ; also on sheet 10 22
VDD_2V5: C534.1 C535.1 C540.1 C541.2 C546.1 C548.1 U125.3(VDDA2P5) U125.9(VDDA2P5) ; also on sheet 10 22
VDDA_1V8: FL1.1 ; also on sheet 13 14 15
CLKOUT0: U7.1(CLKIN) ; also on sheet 41
CPSW2_GPIO_0: J24.14 R589.1 U127.1(D1) U127.2(D2) U127.5(D3) U127.6(D4) U127.8(D5)
CPSW2_LED_1000: J24.12 U128.1(D1) U128.2(D2) U128.5(D3) U128.6(D4) U128.8(D5)
CPSW2_LED_ACT: J24.13 R590.1 U126.1(D1) U126.2(D2) U126.5(D3) U126.6(D4) U126.8(D5)
CPSW_ETH2_D0N: J24.10(MX0-) U125.2(TD_M_A)
CPSW_ETH2_D0P: J24.9(MX0+) U125.1(TD_P_A)
CPSW_ETH2_D1M: J24.8(MX1-) U125.5(TD_M_B)
CPSW_ETH2_D1P: J24.7(MX1+) U125.4(TD_P_B)
CPSW_ETH2_D2M: J24.6(MX2-) U125.8(TD_M_C)
CPSW_ETH2_D2P: J24.5(MX2+) U125.7(TD_P_C)
CPSW_ETH2_D3M: J24.4(MX3-) U125.11(TD_M_D)
CPSW_ETH2_D3P: J24.3(MX3+) U125.10(TD_P_D)
CPSW_ETH2_GPIO_0: R586.1 R588.1 R592.1 R605.2 TP120.1(TP)
CPSW_ETH2_GPIO_1: R584.1 R594.2 R601.1 TP118.1(TP)
CPSW_ETH2_LED0: TP122.1(TP) U125.47(LED_0)
CPSW_ETH2_LED_1000: R591.1 R598.2 R603.1 TP121.1(TP) U125.46(LED_1)
CPSW_ETH2_LED_ACT: R587.1 R596.1 R604.2 TP119.1(TP) U125.45(LED_2)
CPSW_RGMII1_ETH1_CLK: R26.2 ; also on sheet 22
CPSW_RGMII1_RD0: U18.AB16(RGMII1_RD0) ; also on sheet 22
CPSW_RGMII1_RD1: U18.V15(RGMII1_RD1) ; also on sheet 22
CPSW_RGMII1_RD2: U18.W15(RGMII1_RD2) ; also on sheet 22
CPSW_RGMII1_RD3: U18.V14(RGMII1_RD3) ; also on sheet 22
CPSW_RGMII1_RX_CTL: U18.AA15(RGMII1_RX_CTL) ; also on sheet 22
CPSW_RGMII1_RXC: U18.AA16(RGMII1_RXC) ; also on sheet 22
CPSW_RGMII1_TD0: U18.Y17(RGMII1_TD0) ; also on sheet 22
CPSW_RGMII1_TD1: U18.V16(RGMII1_TD1) ; also on sheet 22
CPSW_RGMII1_TD2: U18.Y16(RGMII1_TD2) ; also on sheet 22
CPSW_RGMII1_TD3: U18.AA17(RGMII1_TD3) ; also on sheet 22
CPSW_RGMII1_TX_CTL: U18.W16(RGMII1_TX_CTL) ; also on sheet 22
CPSW_RGMII1_TXC: R322.2 ; also on sheet 22
CPSW_RGMII2_ETH2_CLK: R37.2 U125.15(XI)
CPSW_RGMII2_ETH2_CLK_OUT: TP126.1(TP) U125.18(CLK_OUT)
CPSW_RGMII2_ETH2_RBIAS: C556.2 R611.1 U125.12(RBIAS)
CPSW_RGMII2_MDC: R606.2 R609.2 U125.16(MDC)
CPSW_RGMII2_MDIO: R607.1 R608.2 U125.17(MDIO)
CPSW_RGMII2_RD0: R597.1 R599.2 U18.AA21(RGMII2_RD0) U125.33(RX_D0)
CPSW_RGMII2_RD1: U18.Y20(RGMII2_RD1) U125.34(RX_D1)
CPSW_RGMII2_RD2: R595.2 R600.1 U18.AB21(RGMII2_RD2) U125.35(RX_D2)
CPSW_RGMII2_RD3: U18.AB20(RGMII2_RD3) U125.36(RX_D3)
CPSW_RGMII2_RSTn: R314.1 U42.4(Y) U125.43(RESET_N)
CPSW_RGMII2_RX_CTL: R593.2 R602.2 U18.W18(RGMII2_RX_CTL) U125.38(RX_DV/RX_CTRL)
CPSW_RGMII2_RXC: R582.1 U18.AA20(RGMII2_RXC)
CPSW_RGMII2_TD0: U18.AA19(RGMII2_TD0) U125.28(TX_D0)
CPSW_RGMII2_TD1: U18.Y18(RGMII2_TD1) U125.27(TX_D1)
CPSW_RGMII2_TD2: U18.AA18(RGMII2_TD2) U125.26(TX_D2)
CPSW_RGMII2_TD3: U18.W17(RGMII2_TD3) U125.25(TX_D3)
CPSW_RGMII2_TX_CTL: U18.Y19(RGMII2_TX_CTL) U125.37(TX_EN/TX_CTRL)
CPSW_RGMII2_TXC: R56.2 U125.29(GTX_CLK)
CPSW_RGMII2_TXC_R: R56.1 U18.AB19(RGMII2_TXC)
CPSW_RGMII_INTn: R610.2 U125.44(INT/PWDN) ; also on sheet 22
CPSW_RGMII_TXC_R: R322.1 U18.AB17(RGMII1_TXC)
CSI_REFCLK: R34.2 ; also on sheet 37
ETH2_EARTH: C555.1 J24.15(SH1) J24.16(SH2) R583.1
GPIO_CPSW2_RST: R180.1 R181.1 U42.1(A) ; also on sheet 39
PORz_OUT: U42.3(B) ; also on sheet 19 22 26 41
RESETSTATz: R178.1 ; also on sheet 18 19 20 22 26 37 38 39 40 41
SoC_CLKIN: C19.1 R35.2 R36.2 ; also on sheet 33
SoC_RGMII_MDC: R606.1 ; also on sheet 22 31
SoC_RGMII_MDIO: R608.1 ; also on sheet 22 31
N16943223: R33.1 U7.2(1G)
N20900570: R35.1 U7.3(Y0)
N20900572: R26.1 U7.8(Y1)
N20900574: R37.1 U7.5(Y2)
N20900809: R34.1 U7.7(Y3)
N22498870: R178.2 R182.1 U42.6(C)
N23989710: R582.2 U125.32(RX_CLK)
N23995034: R586.2 U125.39(GPIO_0)
N23995036: R584.2 U125.40(GPIO_1)
N23995142: FL16.2 J24.2(VCC)
N23995224: J24.11 R585.2
N23996283: R588.2 U127.3(G)
N23996295: R587.2 U126.3(G)
N23996384: R591.2 U128.3(G)
N23997204: TP123.1(TP) U125.48(VDDA1P8)
N23997231: TP124.1(TP) U125.13(VDDA1P8)
N24012713: TP125.1(TP) U125.14(XO)

Not connected (* = marked no-connect by the designer): U125 20(JTAG_CLK)* 21(JTAG_TDO)* 22(JTAG_TMS)* 23(JTAG_TDI)*

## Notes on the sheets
sheet 23
- CPSW3G RGMII 2 - ETHERNET PHY
- D-Note :-
  The caps and values used are
  as per the EPHY data sheet
  recommendations.
- D-Note :-
  Refer to DP83867ERGZ-R-EVM when using LAN
  Discrete Transformer Module and RJ45 connector
- R-Note:-
  Ferrite is DNI
- RJ45 CONNECTOR WITH
  INTEGRATED MAGNETICS
- D-Note :-
  Verify the power sequence
  requirements for Two-Supply
  Configuration and Three-Supply
  Configuration
- 100E
- D-Note :-
  Provide provision for
  Series resistor based on
  EPHY selected for RX
  signals near to EPHY
- 100E
- 100E
- 100E
- D-Note :-
  XI clock Input amplitude
  allowed is 1.8V
  irrespective of the IO
  supply. Use a CAP DIVIDER
  when the clock amplified
  is 3.3V
- D-Note :-
  Add a series resistor to the
  SOC GPIO input for isolation
  or testing Refer SK-AM62P-LP
  schematics
- D-Note :-
  ANDing logic could be
  optimized to 2 input AND
  gate. Use RESETSTATz (or
  PORz_OUT) and the SOC IO
  as inputs
- R-Note :-
  Pullup is enabled for SOC GPIO input
  RESETSTATz series resistor is DNI
- D-Note :-
  ANDing logic additionally
  performs level translation
  Verify the Reset IO level
  compatibility before
  optimizing the reset ANDing
  logic. IO level mismatch could
  cause supply leakage and
  affect SOC operation
- Silk: RGMII-2
- PHY ADDRESS = 00001
- Auto-negotiation Enabled
- 10/100/1000 advertised, Auto-MDI-X
- Rx Clock Skew = 2ns
- Tx Clock Skew = 0ns
sheet 24
- SOC MAC INTERFACE
- CLOCK BUFFER FOR SOC AND ETHERNET PHYS
- D-Note :-
  Add an additional bulk cap
- D-Note :-
  C and R must be DNI.
  Mounting these components
  affects the  output clock
  amplitude and board
  performance.
- D-Note :-
  Add series resistors 22 O on the
  Ethernet interface TX (TDx)
  signals near to the SOC
